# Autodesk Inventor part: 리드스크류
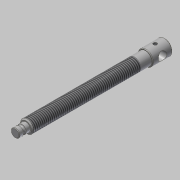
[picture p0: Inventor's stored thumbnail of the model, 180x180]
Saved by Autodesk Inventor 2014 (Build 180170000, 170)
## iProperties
Created: 2019-04
Part Number: 리드스크류
Material: 강철, 연강
Document SubType Name: Modeling
Designer: mduedu
Density: 1 g/cm^3
Appearance: Steel
Author: mduedu
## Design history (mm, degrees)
sketch "스케치1"
  geometry: C1 r 6 at (0, 0); 1 further point
  constraints: 1 centre point, 1 coincident
  dimensions: "d0" = 12 diameter of C1
extrude "돌출1" new body sketch "스케치1" distance "d1" = 110; taper "d2" = 0 deg
sketch "스케치2"
  geometry: C1 r 4 at (0, 0); 1 further point
  constraints: 1 centre point, 1 coincident
  dimensions: "d3" = 8 diameter of C1
extrude "돌출2" join sketch "스케치2" distance "d4" = 10; taper "d5" = 0 deg
sketch "스케치3"
  geometry: C1 r 7 at (0, 0); 1 further point
  constraints: 1 centre point, 1 coincident
  dimensions: "d9" = 14 diameter of C1
extrude "돌출3" join sketch "스케치3" distance "d10" = 18; taper "d11" = 0 deg
feature "스레드1" dims "d12" = 100, "d13" = 0
chamfer "모따기2" distance "d14" = 1; stored, may be unused: second distance "d15" = 2, angle "d16" = 45 deg
chamfer "모따기3" distance "d17" = 0.5; stored, may be unused: second distance "d18" = 2, angle "d19" = 45 deg
chamfer "모따기4" distance "d20" = 0.5; stored, may be unused: second distance "d21" = 2, angle "d22" = 45 deg
sketch "스케치4"
  geometry: L1 (-110, -5)-(-110, 5) reference; L2 (-119.5, 4)-(-119.5, -4) reference; L3 (-119.5, 0)-(-110, 0); C1 r 1.25 at (-115, 4); 1 further point
  constraints: 2 end point, 2 midpoint, 1 centre point
  dimensions: "d23" = 2.5 diameter of C1; "d24" = 5 distance from line of C1.centre L1; "d25" = 4 distance from line of C1.centre L3
revolve "회전1" sketch "스케치4" stored, may be unused: angle "d26" = 90 deg
sketch "스케치5"
  geometry: L1 (0, -6.5)-(0, 6.5) reference; C1 r 4 at (9, 0); 2 further points
  constraints: 1 centre point, 1 horizontal alignment, 1 midpoint
  dimensions: "d27" = 8 diameter of C1; "d28" = 9 distance from line of C1.centre L1
extrude "돌출4" cut sketch "스케치5" stored distance "d29" = 15; taper "d30" = 0 deg
node "작업 평면1"
sketch "스케치6"
  geometry: L1 (0, 6.5)-(0, -6.5) reference; 2 further points
  constraints: 1 horizontal alignment
  dimensions: "d31" = 9 distance from line of point (-9, 0) L1
hole "구멍1" sketch "스케치6" at (-9, 0) diameter "d32" = 3.242; stored, may be unused: countersink angle "d36" = 90 deg, drill point angle "d38" = 118 deg; dims "d33" = 6, "d34" = 4, "d35" = 2, "d37" = 8
node "솔리드1"
